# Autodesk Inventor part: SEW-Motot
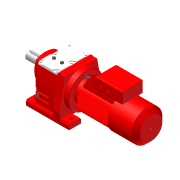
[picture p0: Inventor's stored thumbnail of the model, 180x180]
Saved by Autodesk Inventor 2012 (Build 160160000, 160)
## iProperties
Company: CAD-Verlag
Created: 2008-11
Part Number: SEW-Motot
Document SubType Name: Modeling
Designer: jukr
Density: 1 g/cm^3
Description: R57-1
Material: Standard
Title: SEW Motor
Author: Jürgen Kronas
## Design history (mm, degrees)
derived "R57_1.iam"
node "Volumenkörper1"
node "Volumenkörpern"
node "Oberflächenkörpern"
node "PRODUCT_NAME_1.ipt:1"
node "PRODUCT_NAME_2.ipt:1"
node "PRODUCT_NAME_3.ipt:1"
node "PRODUCT_NAME_4.ipt:1"
node "PRODUCT_NAME_5.ipt:1"
node "PRODUCT_NAME_6.ipt:1"
node "PRODUCT_NAME_7.ipt:1"
node "PRODUCT_NAME_8.ipt:1"
node "PRODUCT_NAME_9.ipt:1"
node "PRODUCT_NAME_10.ipt:1"
node "PRODUCT_NAME_11.ipt:1"
node "PRODUCT_NAME_12.ipt:1"
node "PRODUCT_NAME_13.ipt:1"
node "PRODUCT_NAME_14.ipt:1"
node "PRODUCT_NAME_15.ipt:1"
node "PRODUCT_NAME_16.ipt:1"
node "R57_1.iam_Volumenkörper"
